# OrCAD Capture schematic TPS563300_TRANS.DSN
size Custom; title: TPS563300 3.8-V to 28-V, 3-A Synchronous Buck Converter; rev: 1.1; note: Datasheet: SLUSES9            EVM: NA
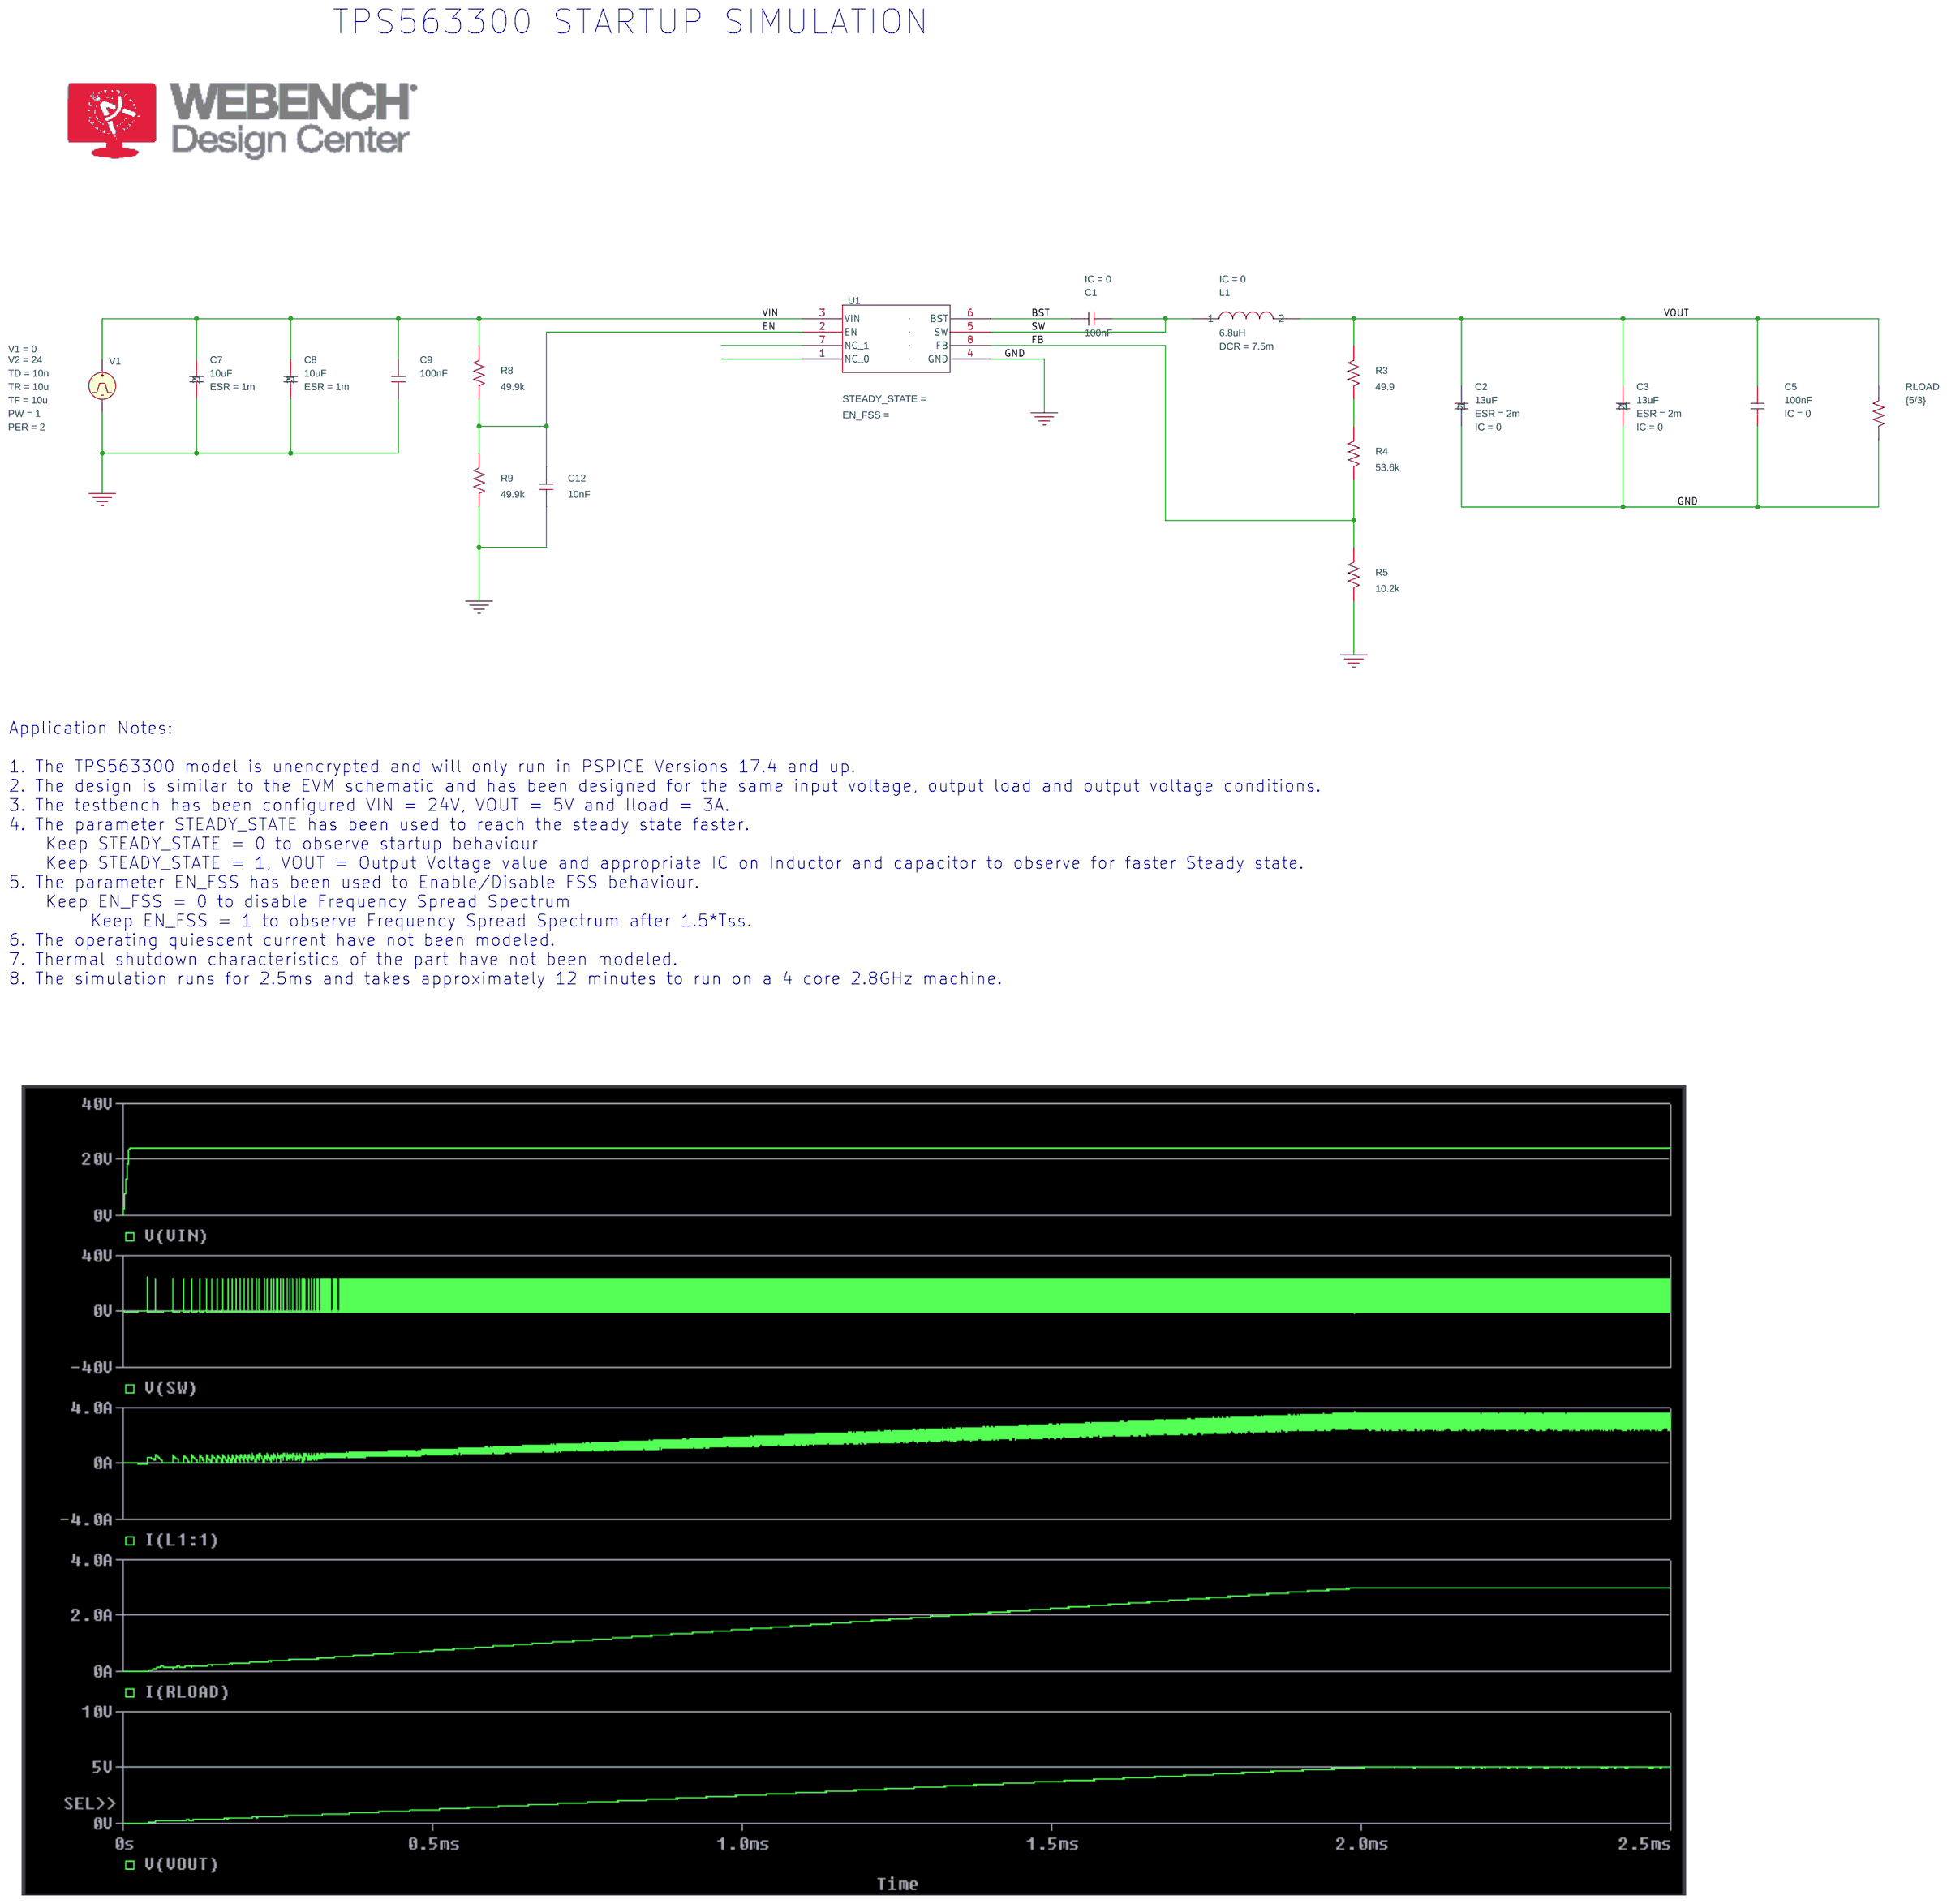
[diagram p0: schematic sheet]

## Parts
C1  100nF  [RAD/CK05]
C2  CESR
C3  CESR
C5  100nF  [RAD/CK05]
C7  CESR
C8  CESR
C9  100nF  [RAD/CK05]
C12  10nF  [RAD/CK05]
L1  LDCR
R3  49.9  [AXRC05]
R4  53.6k  [AXRC05]
R5  10.2k  [AXRC05]
R8  49.9k  [AXRC05]
R9  49.9k  [AXRC05]
RLOAD  {5/3}  [AXRC05]
U1  Value  [DRL0008A-MFG]
V1  VPULSE

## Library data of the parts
C1 C5 = C: IC: 0
C2 = CESR: C: 13uF; ESL: 0; ESR: 2m; IC: 0; PSpiceTemplate: X^@REFDES %1 %2 @MODEL PARAMS: ?C|C=@C||C=10U| ?ESR|ESR=@ESR||ESR=2M| ?ESL|ESL=@ESL||ESL=1N| ?IC|IC=@IC||IC=0|
C3 = CESR_1: C: 13uF; ESL: 0; ESR: 2m; IC: 0; PSpiceTemplate: X^@REFDES %1 %2 @MODEL PARAMS: ?C|C=@C||C=10U| ?ESR|ESR=@ESR||ESR=2M| ?ESL|ESL=@ESL||ESL=1N| ?IC|IC=@IC||IC=0|
C7 = CESR_3: C: 10uF; ESL: 0; ESR: 1m; IC: 0; PSpiceTemplate: X^@REFDES %1 %2 @MODEL PARAMS: ?C|C=@C||C=10U| ?ESR|ESR=@ESR||ESR=2M| ?ESL|ESL=@ESL||ESL=1N| ?IC|IC=@IC||IC=0|
C8 = CESR_2: C: 10uF; ESL: 0; ESR: 1m; IC: 0; PSpiceTemplate: X^@REFDES %1 %2 @MODEL PARAMS: ?C|C=@C||C=10U| ?ESR|ESR=@ESR||ESR=2M| ?ESL|ESL=@ESL||ESL=1N| ?IC|IC=@IC||IC=0|
C9 C12 = C
L1 = LDCR: DCR: 7.5m; IC: 0; L: 6.8uH
R3-R5 R8 R9 RLOAD = R
U1 = TPS563300DRL_TRANS
V1 = VPULSE: PER: 2; PW: 1; TD: 10n; TF: 10u; TR: 10u; V1: 0; V2: 24

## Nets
VIN: C7.1 C8.1 C9.1 R8.1 U1.3(VIN) V1.1(+)
0: C2.2 C3.2 C5.2 C7.2 C8.2 C9.2 C12.2 R5.2 R9.2 RLOAD.2 U1.4(GND) V1.2(-)
BST: C1.1 U1.6(BST)
EN: C12.1 R8.2 R9.1 U1.2(EN)
FB: R4.2 R5.1 U1.8(FB)
SW: C1.2 L1.1 U1.5(SW)
VOUT: C2.1 C3.1 C5.1 L1.2 R3.1 RLOAD.1
N16589384: R3.2 R4.1

Not connected (* = marked no-connect by the designer): U1 1(NC_0) 7(NC_1)

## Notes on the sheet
- TPS563300 STARTUP SIMULATION
- Application Notes:
  1. The TPS563300 model is unencrypted and will only run in PSPICE Versions 17.4 and up.
  2. The design is similar to the EVM schematic and has been designed for the same input voltage, output load and output voltage conditions.
  3. The testbench has been configured VIN = 24V, VOUT = 5V and Iload = 3A.
  4. The parameter STEADY_STATE has been used to reach the steady state faster.
      Keep STEADY_STATE = 0 to observe startup behaviour
      Keep STEADY_STATE = 1, VOUT = Output Voltage value and appropriate IC on Inductor and capacitor to observe for faster Steady state.
  5. The parameter EN_FSS has been used to Enable/Disable FSS behaviour.
      Keep EN_FSS = 0 to disable Frequency Spread Spectrum
  	    Keep EN_FSS = 1 to observe Frequency Spread Spectrum after 1.5*Tss.
  6. The operating quiescent current have not been modeled.
  7. Thermal shutdown characteristics of the part have not been modeled.
  8. The simulation runs for 2.5ms and takes approximately 12 minutes to run on a 4 core 2.8GHz machine.
